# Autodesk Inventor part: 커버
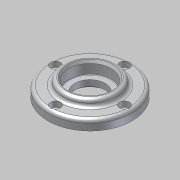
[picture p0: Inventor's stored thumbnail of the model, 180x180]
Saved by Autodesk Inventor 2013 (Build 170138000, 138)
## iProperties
Created: 2014-03
Part Number: 커버
Document SubType Name: Modeling
Designer: SeoGD™[esajin.kr]
Density: 1 g/cm^3
Material: 일반
Author: SeoGD™[esajin.kr]
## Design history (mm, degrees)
sketch "스케치1"
  geometry: C1 r 25 at (0, 0) reference; C2 r 16 at (0, 0) reference; 1 further point
  node "참조1"
  node "참조2"
extrude "돌출1" new body sketch "스케치1" distance "d0" = 6; taper "d1" = 0 deg
extrude "돌출2" join sketch "스케치1" distance "d2" = 3; taper "d3" = 0 deg
sketch "스케치2"
  geometry: C1 r 1.23 at (0, 20.5) reference; 1 further point
hole "구멍1" sketch "스케치2" at (0, 20.5) diameter "d4" = 3.4; stored, may be unused: countersink angle "d8" = 90 deg, drill point angle "d10" = 118 deg; dims "d5" = 6, "d6" = 6, "d7" = 3.3, "d9" = 8
sketch "스케치3"
  geometry: C1 r 16 at (0, 0); 1 further point
  constraints: 1 centre point, 1 coincident
  dimensions: "d11" = 32 diameter of C1
extrude "돌출3" join sketch "스케치3" distance "d12" = 4; taper "d13" = 0 deg
fillet "모깎기1" dims "d14" = 2
hole "구멍2" diameter "d17" = 18; stored, may be unused: countersink angle "d21" = 90 deg, drill point angle "d23" = 118 deg; dims "d15" = 10, "d16" = 10, "d18" = 6, "d19" = 25, "d20" = 7.5, "d22" = 8
chamfer "모따기1" distance "d30" = 1.6; stored, may be unused: second distance "d31" = 2, angle "d32" = 30 deg
fillet "모깎기2" dims "d33" = 0.3
sketch "스케치4"
  geometry: C1 r 16 at (0, 0) reference; C2 r 11.5 at (0, 0); 1 further point
  constraints: 1 centre point, 1 coincident
  dimensions: "d34" = 23 diameter of C2
extrude "돌출4" cut sketch "스케치4" distance "d35" = 2; taper "d36" = 0 deg
fillet "모깎기3" dims "d37" = 3
chamfer "모따기2" distance "d38" = 0.5; stored, may be unused: second distance "d39" = 2, angle "d40" = 45 deg
node "솔리드1"
pattern_circular "원형 패턴2" dims angle "d28" = 360 deg
node "참조3"
